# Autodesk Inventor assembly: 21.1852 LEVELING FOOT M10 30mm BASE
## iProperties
Created: 2007-03
Part Number: 21.1852 LEVELING FOOT M10 30mm BASE
Document SubType Name: Assembly
Designer: Andy Moles
Author: Andy Moles
